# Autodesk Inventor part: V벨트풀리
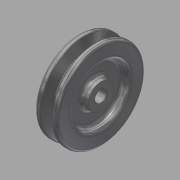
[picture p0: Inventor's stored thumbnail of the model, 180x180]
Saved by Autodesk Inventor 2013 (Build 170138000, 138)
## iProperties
Created: 2015-11
Part Number: V벨트풀리
Material: 강철, 탄소
Document SubType Name: Modeling
Designer: mduedu
Density: 1 g/cm^3
Author: mduedu
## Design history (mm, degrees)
sketch "스케치1"
  geometry: L1 (-9.5, 0)-(9.5, 0); L2 (0, 0)-(0, 37.7); L3 (-4.825, 37.7)-(-9.5, 37.7); L4 (-9.5, 37.7)-(-9.5, 0); L5 (0, 28.7)-(-2.074, 28.7); L6 (-2.074, 28.7)-(-4.825, 37.7); L7 (4.825, 37.7)-(9.5, 37.7); L8 (9.5, 37.7)-(9.5, 0); L9 (0, 28.7)-(2.074, 28.7); L10 (2.074, 28.7)-(4.825, 37.7); L11 (-9.5, 35)-(9.5, 35); 3 further points
  constraints: 22 end point, 7 point on line, 4 perpendicular, 3 symmetric about line, 1 coincident, 1 horizontal, 1 horizontal alignment, 1 midpoint, 1 vertical
  dimensions: "d0" = 19 distance of L1.start L1.end; "d2" = 75.4 diameter of L2.end L1 (derived); "d3" = 34 deg angle of L10 L6; "d4" = 6.3 distance between parallel lines of L11 L9; "d5" = 2.7 distance between parallel lines of L7 L11; "d6" = 8 distance of point (4, 35) point (-4, 35); "d7" = 70 diameter of L11 L1
revolve "회전1" sketch "스케치1" stored, may be unused: angle "d8" = 90 deg
sketch "스케치2"
  geometry: C1 r 24 at (0, 0); C2 r 11 at (0, 0); 1 further point
  constraints: 2 centre point, 2 coincident
  dimensions: "d9" = 48 diameter of C1; "d10" = 22 diameter of C2
extrude "돌출1" cut sketch "스케치2" distance "d11" = 6; taper "d12" = 0 deg
fillet "모깎기1" dims "d13" = 3
fillet "모깎기2" dims "d14" = 3
fillet "모깎기3" dims "d15" = 1, "d16" = 0.5, "d17" = 2
hole "구멍1" diameter "d20" = 10; stored, may be unused: countersink angle "d24" = 90 deg, drill point angle "d26" = 118 deg; dims "d18" = 10, "d19" = 10, "d21" = 6, "d22" = 4, "d23" = 2, "d25" = 8
sketch "스케치3"
  geometry: L1 (-1.5, 0)-(1.5, 0); L2 (1.5, 0)-(1.5, 6.4); L3 (1.5, 6.4)-(-1.5, 6.4); L4 (-1.5, 6.4)-(-1.5, 0); 2 further points
  constraints: 8 end point, 2 parallel, 1 coincident, 1 horizontal, 1 midpoint, 1 perpendicular
  dimensions: "d27" = 3 distance of L2.end L3.end; "d29" = 6.4 distance of L3.end L1.start
extrude "돌출2" cut sketch "스케치3" stored distance "d30" = 6; taper "d31" = 0 deg
chamfer "모따기1" distance "d32" = 0.5; stored, may be unused: second distance "d33" = 2, angle "d34" = 45 deg
node "솔리드1"
mirror "대칭1"
